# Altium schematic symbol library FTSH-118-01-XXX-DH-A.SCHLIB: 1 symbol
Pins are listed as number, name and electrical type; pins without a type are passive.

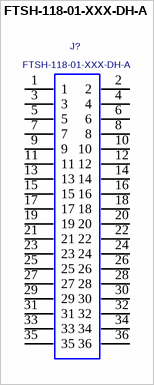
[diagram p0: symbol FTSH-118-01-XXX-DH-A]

## FTSH-118-01-XXX-DH-A
designator J?
.050 X .050 C.L. DOUBLE HORIZONTAL TERMINAL STRIP.; MANUFACTURER: SAMTEC
footprint FTSH-118-01-XXX-DH-A
pins: 1, 2, 3, 4, 5, 6, 7, 8, 9, 10, 11, 12, 13, 14, 15, 16, 17, 18, 19, 20, 21, 22, 23, 24, 25, 26, 27, 28, 29, 30, 31, 32, 33, 34, 35, 36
